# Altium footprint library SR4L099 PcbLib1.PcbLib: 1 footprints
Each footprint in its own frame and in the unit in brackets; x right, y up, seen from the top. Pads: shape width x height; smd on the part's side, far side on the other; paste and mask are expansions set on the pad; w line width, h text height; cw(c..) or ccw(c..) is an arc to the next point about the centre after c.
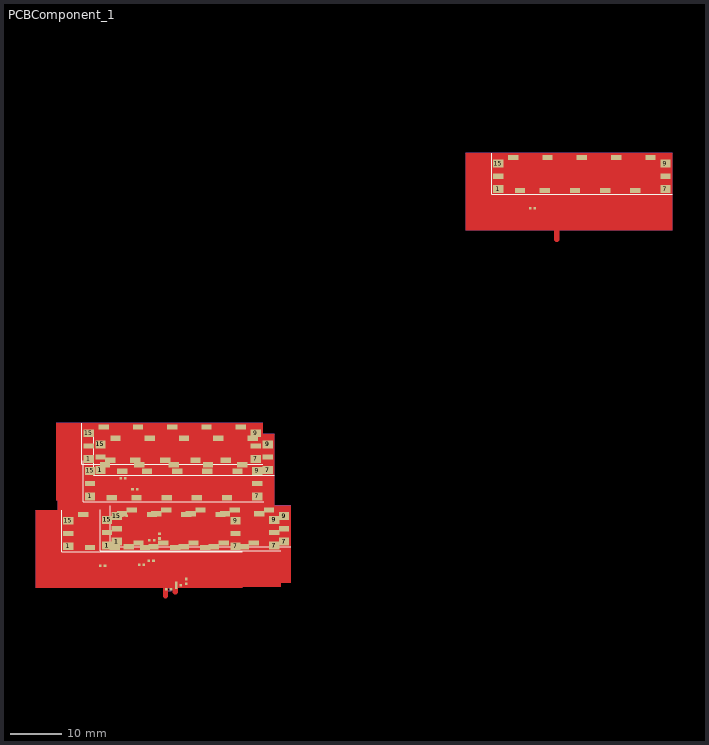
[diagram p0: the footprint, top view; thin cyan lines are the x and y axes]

## PCBComponent_1 [mm]
pads (200):
  rect 2x1.5 smd: 1(-1249.27,-1295.556) 1(-1245.325,-1278.607) 1(-1245.055,-1285.889) 1(-1243.039,-1280.766) 1(-1243.039,-1280.766) 1(-1241.769,-1295.397) 1(-1241.769,-1295.397) 1(-1239.864,-1294.635) 1(-1239.864,-1294.635) 1(-1165.938,-1226.316) 7(-1216.87,-1295.556) 7(-1212.925,-1278.607) 7(-1212.655,-1285.889) 7(-1210.639,-1280.766) 7(-1210.639,-1280.766) 7(-1209.369,-1295.397) 7(-1209.369,-1295.397) 7(-1207.464,-1294.635) 7(-1207.464,-1294.635) 7(-1133.538,-1226.316) 9(-1216.87,-1290.606) 9(-1212.925,-1273.657) 9(-1212.655,-1280.939) 9(-1210.639,-1275.816) 9(-1210.639,-1275.816) 9(-1209.369,-1290.447) 9(-1209.369,-1290.447) 9(-1207.464,-1289.685) 9(-1207.464,-1289.685) 9(-1133.538,-1221.366) 15(-1249.27,-1290.606) 15(-1245.325,-1273.657) 15(-1245.055,-1280.939) 15(-1243.039,-1275.816) 15(-1243.039,-1275.816) 15(-1241.769,-1290.447) 15(-1241.769,-1290.447) 15(-1239.864,-1289.685) 15(-1239.864,-1289.685) 15(-1165.938,-1221.366)
  rect 0.5x0.5 smd: 1(-1243.065,-1299.306) 1(-1239.12,-1282.357) 1(-1238.85,-1289.639) 1(-1236.834,-1284.516) 1(-1236.834,-1284.516) 1(-1235.564,-1299.147) 1(-1235.564,-1299.147) 1(-1233.659,-1298.385) 1(-1233.659,-1298.385) 1(-1233.557,-1294.393) 1(-1231.601,-1294.042) 1(-1230.271,-1303.901) 1(-1230.271,-1303.901) 1(-1228.366,-1303.139) 1(-1228.366,-1303.139) 1(-1228.315,-1303.55) 1(-1228.315,-1303.55) 1(-1226.41,-1302.788) 1(-1226.41,-1302.788) 1(-1159.733,-1230.066) 2(-1242.165,-1299.306) 2(-1238.22,-1282.357) 2(-1237.95,-1289.639) 2(-1235.934,-1284.516) 2(-1235.934,-1284.516) 2(-1234.664,-1299.147) 2(-1234.664,-1299.147) 2(-1232.759,-1298.385) 2(-1232.759,-1298.385) 2(-1232.657,-1294.393) 2(-1231.601,-1293.143) 2(-1229.371,-1303.901) 2(-1229.371,-1303.901) 2(-1228.315,-1302.651) 2(-1228.315,-1302.651) 2(-1227.466,-1303.139) 2(-1227.466,-1303.139) 2(-1226.41,-1301.889) 2(-1226.41,-1301.889) 2(-1158.833,-1230.066)
  rect 2x1 smd: 2(-1245.07,-1295.806) 2(-1241.125,-1278.857) 2(-1240.855,-1286.139) 2(-1238.839,-1281.016) 2(-1238.839,-1281.016) 2(-1237.569,-1295.647) 2(-1237.569,-1295.647) 2(-1235.664,-1294.885) 2(-1235.664,-1294.885) 2(-1161.738,-1226.566) 3(-1240.27,-1295.806) 3(-1236.325,-1278.857) 3(-1236.055,-1286.139) 3(-1234.039,-1281.016) 3(-1234.039,-1281.016) 3(-1232.769,-1295.647) 3(-1232.769,-1295.647) 3(-1230.864,-1294.885) 3(-1230.864,-1294.885) 3(-1156.938,-1226.566) 4(-1234.42,-1295.806) 4(-1230.475,-1278.857) 4(-1230.205,-1286.139) 4(-1228.189,-1281.016) 4(-1228.189,-1281.016) 4(-1226.919,-1295.647) 4(-1226.919,-1295.647) 4(-1225.014,-1294.885) 4(-1225.014,-1294.885) 4(-1151.088,-1226.566) 5(-1228.57,-1295.806) 5(-1224.625,-1278.857) 5(-1224.355,-1286.139) 5(-1222.339,-1281.016) 5(-1222.339,-1281.016) 5(-1221.069,-1295.647) 5(-1221.069,-1295.647) 5(-1219.164,-1294.885) 5(-1219.164,-1294.885) 5(-1145.238,-1226.566) 6(-1222.72,-1295.806) 6(-1218.775,-1278.857) 6(-1218.505,-1286.139) 6(-1216.489,-1281.016) 6(-1216.489,-1281.016) 6(-1215.219,-1295.647) 6(-1215.219,-1295.647) 6(-1213.314,-1294.885) 6(-1213.314,-1294.885) 6(-1139.388,-1226.566) 8(-1216.87,-1293.056) 8(-1212.925,-1276.107) 8(-1212.655,-1283.389) 8(-1210.639,-1278.266) 8(-1210.639,-1278.266) 8(-1209.369,-1292.897) 8(-1209.369,-1292.897) 8(-1207.464,-1292.135) 8(-1207.464,-1292.135) 8(-1133.538,-1223.816) 10(-1219.77,-1289.406) 10(-1215.825,-1272.457) 10(-1215.555,-1279.739) 10(-1213.539,-1274.616) 10(-1213.539,-1274.616) 10(-1212.269,-1289.247) 10(-1212.269,-1289.247) 10(-1210.364,-1288.485) 10(-1210.364,-1288.485) 10(-1136.438,-1220.166) 11(-1226.42,-1289.406) 11(-1222.475,-1272.457) 11(-1222.205,-1279.739) 11(-1220.189,-1274.616) 11(-1220.189,-1274.616) 11(-1218.919,-1289.247) 11(-1218.919,-1289.247) 11(-1217.014,-1288.485) 11(-1217.014,-1288.485) 11(-1143.088,-1220.166) 12(-1233.07,-1289.406) 12(-1229.125,-1272.457) 12(-1228.855,-1279.739) 12(-1226.839,-1274.616) 12(-1226.839,-1274.616) 12(-1225.569,-1289.247) 12(-1225.569,-1289.247) 12(-1223.664,-1288.485) 12(-1223.664,-1288.485) 12(-1149.738,-1220.166) 13(-1239.72,-1289.406) 13(-1235.775,-1272.457) 13(-1235.505,-1279.739) 13(-1233.489,-1274.616) 13(-1233.489,-1274.616) 13(-1232.219,-1289.247) 13(-1232.219,-1289.247) 13(-1230.314,-1288.485) 13(-1230.314,-1288.485) 13(-1156.388,-1220.166) 14(-1246.37,-1289.406) 14(-1242.425,-1272.457) 14(-1242.155,-1279.739) 14(-1240.139,-1274.616) 14(-1240.139,-1274.616) 14(-1238.869,-1289.247) 14(-1238.869,-1289.247) 14(-1236.964,-1288.485) 14(-1236.964,-1288.485) 14(-1163.038,-1220.166) 16(-1249.27,-1293.056) 16(-1245.325,-1276.107) 16(-1245.055,-1283.389) 16(-1243.039,-1278.266) 16(-1243.039,-1278.266) 16(-1241.769,-1292.897) 16(-1241.769,-1292.897) 16(-1239.864,-1292.135) 16(-1239.864,-1292.135) 16(-1165.938,-1223.816)
Top Layer:
  rectangle: -1152.965,-1233.816 -1151.988,-1230.566
  rectangle: -1156.938,-1230.566 -1151.988,-1229.566
  rectangle: -1161.988,-1229.866 -1160.488,-1226.066
  rectangle: -1158.238,-1229.866 -1156.738,-1226.066
  rectangle: -1232.082,-1293.389 -1231.105,-1290.139
  rectangle: -1236.055,-1290.139 -1231.105,-1289.139
  rectangle: -1241.105,-1289.439 -1239.605,-1285.639
  rectangle: -1237.355,-1289.439 -1235.855,-1285.639
  rectangle: -1226.891,-1302.135 -1225.914,-1298.885
  rectangle: -1230.864,-1298.885 -1225.914,-1297.885
  rectangle: -1235.914,-1298.185 -1234.414,-1294.385
  rectangle: -1232.164,-1298.185 -1230.664,-1294.385
  rectangle: -1226.891,-1302.135 -1225.914,-1298.885
  rectangle: -1230.864,-1298.885 -1225.914,-1297.885
  rectangle: -1235.914,-1298.185 -1234.414,-1294.385
  rectangle: -1232.164,-1298.185 -1230.664,-1294.385
  rectangle: -1228.796,-1302.897 -1227.819,-1299.647
  rectangle: -1232.769,-1299.647 -1227.819,-1298.647
  rectangle: -1237.819,-1298.947 -1236.319,-1295.147
  rectangle: -1234.069,-1298.947 -1232.569,-1295.147
  rectangle: -1228.796,-1302.897 -1227.819,-1299.647
  rectangle: -1232.769,-1299.647 -1227.819,-1298.647
  rectangle: -1237.819,-1298.947 -1236.319,-1295.147
  rectangle: -1234.069,-1298.947 -1232.569,-1295.147
  rectangle: -1230.066,-1288.266 -1229.089,-1285.016
  rectangle: -1234.039,-1285.016 -1229.089,-1284.016
  rectangle: -1239.089,-1284.316 -1237.589,-1280.516
  rectangle: -1235.339,-1284.316 -1233.839,-1280.516
  rectangle: -1230.066,-1288.266 -1229.089,-1285.016
  rectangle: -1234.039,-1285.016 -1229.089,-1284.016
  rectangle: -1239.089,-1284.316 -1237.589,-1280.516
  rectangle: -1235.339,-1284.316 -1233.839,-1280.516
  rectangle: -1232.352,-1286.107 -1231.375,-1282.857
  rectangle: -1236.325,-1282.857 -1231.375,-1281.857
  rectangle: -1241.375,-1282.157 -1239.875,-1278.357
  rectangle: -1237.625,-1282.157 -1236.125,-1278.357
  rectangle: -1236.297,-1303.056 -1235.32,-1299.806
  rectangle: -1240.27,-1299.806 -1235.32,-1298.806
  rectangle: -1245.32,-1299.106 -1243.82,-1295.306
  rectangle: -1241.57,-1299.106 -1240.07,-1295.306
  pour cut-out: -1172.238,-1234.316 -1132.238,-1234.316 -1132.238,-1219.366 -1172.238,-1219.366
  region: -1161.738,-1230.566 -1161.738,-1229.566 -1159.553,-1229.566 -1159.553,-1230.567
  region: -1156.938,-1230.566 -1156.938,-1229.566 -1159.038,-1229.566 -1159.038,-1230.566
  region: -1161.738,-1230.566 -1170.238,-1230.566 -1170.238,-1228.066 -1161.738,-1228.066
  pour cut-out: -1251.355,-1293.889 -1211.355,-1293.889 -1211.355,-1278.939 -1251.355,-1278.939
  region: -1240.855,-1290.139 -1240.855,-1289.139 -1238.67,-1289.139 -1238.67,-1290.14
  region: -1236.055,-1290.139 -1236.055,-1289.139 -1238.155,-1289.139 -1238.155,-1290.139
  region: -1240.855,-1290.139 -1249.355,-1290.139 -1249.355,-1287.639 -1240.855,-1287.639
  pour cut-out: -1246.164,-1302.635 -1206.164,-1302.635 -1206.164,-1287.685 -1246.164,-1287.685
  region: -1235.664,-1298.885 -1235.664,-1297.885 -1233.479,-1297.885 -1233.479,-1298.886
  region: -1230.864,-1298.885 -1230.864,-1297.885 -1232.964,-1297.885 -1232.964,-1298.885
  region: -1235.664,-1298.885 -1244.164,-1298.885 -1244.164,-1296.385 -1235.664,-1296.385
  pour cut-out: -1246.164,-1302.635 -1206.164,-1302.635 -1206.164,-1287.685 -1246.164,-1287.685
  region: -1235.664,-1298.885 -1235.664,-1297.885 -1233.479,-1297.885 -1233.479,-1298.886
  region: -1230.864,-1298.885 -1230.864,-1297.885 -1232.964,-1297.885 -1232.964,-1298.885
  region: -1235.664,-1298.885 -1244.164,-1298.885 -1244.164,-1296.385 -1235.664,-1296.385
  pour cut-out: -1248.069,-1303.397 -1208.069,-1303.397 -1208.069,-1288.447 -1248.069,-1288.447
  region: -1237.569,-1299.647 -1237.569,-1298.647 -1235.384,-1298.647 -1235.384,-1299.648
  region: -1232.769,-1299.647 -1232.769,-1298.647 -1234.869,-1298.647 -1234.869,-1299.647
  region: -1237.569,-1299.647 -1246.069,-1299.647 -1246.069,-1297.147 -1237.569,-1297.147
  pour cut-out: -1248.069,-1303.397 -1208.069,-1303.397 -1208.069,-1288.447 -1248.069,-1288.447
  region: -1237.569,-1299.647 -1237.569,-1298.647 -1235.384,-1298.647 -1235.384,-1299.648
  region: -1232.769,-1299.647 -1232.769,-1298.647 -1234.869,-1298.647 -1234.869,-1299.647
  region: -1237.569,-1299.647 -1246.069,-1299.647 -1246.069,-1297.147 -1237.569,-1297.147
  pour cut-out: -1249.339,-1288.766 -1209.339,-1288.766 -1209.339,-1273.816 -1249.339,-1273.816
  region: -1238.839,-1285.016 -1238.839,-1284.016 -1236.654,-1284.016 -1236.654,-1285.017
  region: -1234.039,-1285.016 -1234.039,-1284.016 -1236.139,-1284.016 -1236.139,-1285.016
  region: -1238.839,-1285.016 -1247.339,-1285.016 -1247.339,-1282.516 -1238.839,-1282.516
  pour cut-out: -1249.339,-1288.766 -1209.339,-1288.766 -1209.339,-1273.816 -1249.339,-1273.816
  region: -1238.839,-1285.016 -1238.839,-1284.016 -1236.654,-1284.016 -1236.654,-1285.017
  region: -1234.039,-1285.016 -1234.039,-1284.016 -1236.139,-1284.016 -1236.139,-1285.016
  region: -1238.839,-1285.016 -1247.339,-1285.016 -1247.339,-1282.516 -1238.839,-1282.516
  pour cut-out: -1251.625,-1286.607 -1211.625,-1286.607 -1211.625,-1271.657 -1251.625,-1271.657
  region: -1241.125,-1282.857 -1241.125,-1281.857 -1238.94,-1281.857 -1238.94,-1282.858
  region: -1236.325,-1282.857 -1236.325,-1281.857 -1238.425,-1281.857 -1238.425,-1282.857
  region: -1241.125,-1282.857 -1249.625,-1282.857 -1249.625,-1280.357 -1241.125,-1280.357
  pour cut-out: -1255.57,-1303.556 -1215.57,-1303.556 -1215.57,-1288.606 -1255.57,-1288.606
  region: -1245.07,-1299.806 -1245.07,-1298.806 -1242.885,-1298.806 -1242.885,-1299.807
  region: -1240.27,-1299.806 -1240.27,-1298.806 -1242.37,-1298.806 -1242.37,-1299.806
  region: -1245.07,-1299.806 -1253.57,-1299.806 -1253.57,-1297.306 -1245.07,-1297.306
  lines w1: -1233.73,-1295.639 -1233.73,-1289.939 ; -1154.613,-1236.066 -1154.613,-1230.366 ; -1230.444,-1305.147 -1230.444,-1299.447 -1230.444,-1305.147 ; -1228.539,-1304.385 -1228.539,-1298.685 -1228.539,-1304.385
Bottom Layer:
  pour cut-out: -1172.238,-1234.316 -1132.238,-1234.316 -1132.238,-1219.366 -1172.238,-1219.366
  pour cut-out: -1251.355,-1293.889 -1211.355,-1293.889 -1211.355,-1278.939 -1251.355,-1278.939
  pour cut-out: -1246.164,-1302.635 -1206.164,-1302.635 -1206.164,-1287.685 -1246.164,-1287.685
  pour cut-out: -1246.164,-1302.635 -1206.164,-1302.635 -1206.164,-1287.685 -1246.164,-1287.685
  pour cut-out: -1248.069,-1303.397 -1208.069,-1303.397 -1208.069,-1288.447 -1248.069,-1288.447
  pour cut-out: -1248.069,-1303.397 -1208.069,-1303.397 -1208.069,-1288.447 -1248.069,-1288.447
  pour cut-out: -1249.339,-1288.766 -1209.339,-1288.766 -1209.339,-1273.816 -1249.339,-1273.816
  pour cut-out: -1249.339,-1288.766 -1209.339,-1288.766 -1209.339,-1273.816 -1249.339,-1273.816
  pour cut-out: -1251.625,-1286.607 -1211.625,-1286.607 -1211.625,-1271.657 -1251.625,-1271.657
  pour cut-out: -1255.57,-1303.556 -1215.57,-1303.556 -1215.57,-1288.606 -1255.57,-1288.606
Top Overlay:
  lines w0.01: -1236.339,-1281.816 -1236.339,-1281.816 ; -1236.339,-1281.816 -1236.339,-1281.816 ; -1235.069,-1296.447 -1235.069,-1296.447 ; -1235.069,-1296.447 -1235.069,-1296.447 ; -1233.164,-1295.685 -1233.164,-1295.685 ; -1233.164,-1295.685 -1233.164,-1295.685 ; -1209.339,-1281.816 -1209.339,-1281.816 ; -1209.339,-1281.816 -1209.339,-1281.816 ; -1208.069,-1296.447 -1208.069,-1296.447 ; -1208.069,-1296.447 -1208.069,-1296.447 ; -1206.164,-1295.685 -1206.164,-1295.685 ; -1206.164,-1295.685 -1206.164,-1295.685 ; -1242.57,-1296.606 -1242.57,-1296.606 ; -1238.625,-1279.657 -1238.625,-1279.657 ; -1238.355,-1286.939 -1238.355,-1286.939 ; -1215.57,-1296.606 -1215.57,-1296.606 ; -1211.625,-1279.657 -1211.625,-1279.657 ; -1211.355,-1286.939 -1211.355,-1286.939 ; -1159.238,-1227.366 -1159.238,-1227.366 ; -1132.238,-1227.366 -1132.238,-1227.366
  lines w0.03: -1250.57,-1296.606 -1215.57,-1296.606 ; -1246.625,-1279.657 -1211.625,-1279.657 ; -1246.355,-1286.939 -1211.355,-1286.939 ; -1167.238,-1227.366 -1132.238,-1227.366 ; -1244.339,-1281.816 -1209.339,-1281.816 -1244.339,-1281.816 ; -1243.069,-1296.447 -1208.069,-1296.447 -1243.069,-1296.447 ; -1241.164,-1295.685 -1206.164,-1295.685 -1241.164,-1295.685
  lines w0.05: -1250.57,-1296.606 -1250.57,-1288.606 ; -1246.625,-1279.657 -1246.625,-1271.657 ; -1246.355,-1286.939 -1246.355,-1278.939 ; -1242.57,-1296.606 -1215.57,-1296.606 ; -1238.625,-1279.657 -1211.625,-1279.657 ; -1238.355,-1286.939 -1211.355,-1286.939 ; -1167.238,-1227.366 -1167.238,-1219.366 ; -1159.238,-1227.366 -1132.238,-1227.366 ; -1244.339,-1281.816 -1244.339,-1273.816 -1244.339,-1281.816 ; -1243.069,-1296.447 -1243.069,-1288.447 -1243.069,-1296.447 ; -1241.164,-1295.685 -1241.164,-1287.685 -1241.164,-1295.685 ; -1236.339,-1281.816 -1209.339,-1281.816 -1236.339,-1281.816 ; -1235.069,-1296.447 -1208.069,-1296.447 -1235.069,-1296.447 ; -1233.164,-1295.685 -1206.164,-1295.685 -1233.164,-1295.685
Mechanical 1:
  lines w0.013: -1255.57,-1288.556 -1215.57,-1288.556 ; -1251.625,-1271.607 -1211.625,-1271.607 ; -1251.355,-1278.889 -1211.355,-1278.889 ; -1172.238,-1219.316 -1132.238,-1219.316 ; -1249.339,-1273.766 -1209.339,-1273.766 -1249.339,-1273.766 ; -1248.069,-1288.397 -1208.069,-1288.397 -1248.069,-1288.397 ; -1246.164,-1287.635 -1206.164,-1287.635 -1246.164,-1287.635
Mechanical 13:
  lines w0.1: -1236.907,-1284.787 -1236.907,-1284.237 ; -1236.907,-1284.787 -1235.857,-1284.787 ; -1236.907,-1284.787 -1236.907,-1284.237 ; -1236.907,-1284.787 -1235.857,-1284.787 ; -1236.907,-1284.237 -1235.857,-1284.237 ; -1236.907,-1284.237 -1235.857,-1284.237 ; -1235.857,-1284.787 -1235.857,-1284.237 ; -1235.857,-1284.787 -1235.857,-1284.237 ; -1235.637,-1299.418 -1235.637,-1298.868 ; -1235.637,-1299.418 -1234.587,-1299.418 ; -1235.637,-1299.418 -1235.637,-1298.868 ; -1235.637,-1299.418 -1234.587,-1299.418 ; -1235.637,-1298.868 -1234.587,-1298.868 ; -1235.637,-1298.868 -1234.587,-1298.868 ; -1234.587,-1299.418 -1234.587,-1298.868 ; -1234.587,-1299.418 -1234.587,-1298.868 ; -1233.732,-1298.656 -1233.732,-1298.106 ; -1233.732,-1298.656 -1232.682,-1298.656 ; -1233.732,-1298.656 -1233.732,-1298.106 ; -1233.732,-1298.656 -1232.682,-1298.656 ; -1233.732,-1298.106 -1232.682,-1298.106 ; -1233.732,-1298.106 -1232.682,-1298.106 ; -1232.682,-1298.656 -1232.682,-1298.106 ; -1232.682,-1298.656 -1232.682,-1298.106 ; -1230.344,-1304.172 -1230.344,-1303.622 ; -1230.344,-1304.172 -1229.294,-1304.172 ; -1230.344,-1304.172 -1230.344,-1303.622 ; -1230.344,-1304.172 -1229.294,-1304.172 ; -1230.344,-1303.622 -1229.294,-1303.622 ; -1230.344,-1303.622 -1229.294,-1303.622 ; -1229.294,-1304.172 -1229.294,-1303.622 ; -1229.294,-1304.172 -1229.294,-1303.622 ; -1228.594,-1303.624 -1228.594,-1302.574 ; -1228.594,-1303.624 -1228.044,-1303.624 ; -1228.594,-1303.624 -1228.594,-1302.574 ; -1228.594,-1303.624 -1228.044,-1303.624 ; -1228.594,-1302.574 -1228.044,-1302.574 ; -1228.594,-1302.574 -1228.044,-1302.574 ; -1228.439,-1303.41 -1228.439,-1302.86 ; -1228.439,-1303.41 -1227.389,-1303.41 ; -1228.439,-1303.41 -1228.439,-1302.86 ; -1228.439,-1303.41 -1227.389,-1303.41 ; -1228.439,-1302.86 -1227.389,-1302.86 ; -1228.439,-1302.86 -1227.389,-1302.86 ; -1228.044,-1303.624 -1228.044,-1302.574 ; -1228.044,-1303.624 -1228.044,-1302.574 ; -1227.389,-1303.41 -1227.389,-1302.86 ; -1227.389,-1303.41 -1227.389,-1302.86 ; -1226.689,-1302.862 -1226.689,-1301.812 ; -1226.689,-1302.862 -1226.139,-1302.862 ; -1226.689,-1302.862 -1226.689,-1301.812 ; -1226.689,-1302.862 -1226.139,-1302.862 ; -1226.689,-1301.812 -1226.139,-1301.812 ; -1226.689,-1301.812 -1226.139,-1301.812 ; -1226.139,-1302.862 -1226.139,-1301.812 ; -1226.139,-1302.862 -1226.139,-1301.812 ; -1243.138,-1299.577 -1243.138,-1299.027 -1242.088,-1299.027 -1242.088,-1299.577 -1243.138,-1299.577 ; -1239.193,-1282.628 -1239.193,-1282.078 -1238.143,-1282.078 -1238.143,-1282.628 -1239.193,-1282.628 ; -1238.923,-1289.91 -1238.923,-1289.36 -1237.873,-1289.36 -1237.873,-1289.91 -1238.923,-1289.91 ; -1233.63,-1294.664 -1233.63,-1294.114 -1232.58,-1294.114 -1232.58,-1294.664 -1233.63,-1294.664 ; -1231.88,-1294.116 -1231.88,-1293.066 -1231.33,-1293.066 -1231.33,-1294.116 -1231.88,-1294.116 ; -1159.806,-1230.337 -1159.806,-1229.787 -1158.756,-1229.787 -1158.756,-1230.337 -1159.806,-1230.337
3D body: height 0.55, standoff 0, extent -1159.806,-1230.337 -1158.756,-1229.787
3D body: height 0.55, standoff 0, extent -1231.88,-1294.116 -1231.33,-1293.066
3D body: height 0.55, standoff 0, extent -1238.923,-1289.91 -1237.873,-1289.36
3D body: height 0.55, standoff 0, extent -1233.63,-1294.664 -1232.58,-1294.114
3D body: height 0.55, standoff 0, extent -1226.689,-1302.862 -1226.139,-1301.812
3D body: height 0.55, standoff 0, extent -1233.732,-1298.656 -1232.682,-1298.106
3D body: height 0.55, standoff 0, extent -1228.439,-1303.41 -1227.389,-1302.86
3D body: height 0.55, standoff 0, extent -1226.689,-1302.862 -1226.139,-1301.812
3D body: height 0.55, standoff 0, extent -1233.732,-1298.656 -1232.682,-1298.106
3D body: height 0.55, standoff 0, extent -1228.439,-1303.41 -1227.389,-1302.86
3D body: height 0.55, standoff 0, extent -1228.594,-1303.624 -1228.044,-1302.574
3D body: height 0.55, standoff 0, extent -1235.637,-1299.418 -1234.587,-1298.868
3D body: height 0.55, standoff 0, extent -1230.344,-1304.172 -1229.294,-1303.622
3D body: height 0.55, standoff 0, extent -1228.594,-1303.624 -1228.044,-1302.574
3D body: height 0.55, standoff 0, extent -1235.637,-1299.418 -1234.587,-1298.868
3D body: height 0.55, standoff 0, extent -1230.344,-1304.172 -1229.294,-1303.622
3D body: height 0.55, standoff 0, extent -1236.907,-1284.787 -1235.857,-1284.237
3D body: height 0.55, standoff 0, extent -1236.907,-1284.787 -1235.857,-1284.237
3D body: height 0.55, standoff 0, extent -1239.193,-1282.628 -1238.143,-1282.078
3D body: height 0.55, standoff 0, extent -1243.138,-1299.577 -1242.088,-1299.027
